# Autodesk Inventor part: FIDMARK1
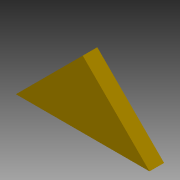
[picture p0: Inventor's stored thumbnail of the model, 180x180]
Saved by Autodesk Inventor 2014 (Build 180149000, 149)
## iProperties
Shininess: 64.0
Length Units: 11272
Angle Units: 11279
Time Units: 11290
Mass Units: 11286
Length Display Precision: 3
Angle Display Precision: 2
Compacted: True
Part Number: FIDMARK1
Document SubType Name: Modeling
Created: 2003-04
Designer: t_enrig
Manufacturer: Standard
Standards Organization: Custom
Density: 1 g/cm^3
Mass: 0.00059485 g
Surface Area: 0.0595919 cm^2
Volume: 0.00059485 cm^3
Material: Generic
Appearance: TranslatedColorStyle
Density: 0.0
Volumn: 0.0
Area: 0.0
PropertySet Name: Model Information
Control State: 0
Master: False
Checked Out: False
Author: t_enrig
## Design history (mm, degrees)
feature "Base1"
body "Solid1"
